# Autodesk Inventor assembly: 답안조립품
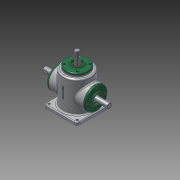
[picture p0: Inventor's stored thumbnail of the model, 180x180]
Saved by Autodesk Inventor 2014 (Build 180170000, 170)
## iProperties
Created: 2015-10
Part Number: 답안조립품
Document SubType Name: Assembly
Designer: Administrator
Author: Administrator
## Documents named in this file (14)
- C:\Users\Administrator\Desktop\451007V1019\답안조립품.iam
- C:\Users\Administrator\Desktop\451007V1019\1-본체.ipt
- C:\Users\Administrator\Desktop\451007V1019\M4.ipt
- C:\Users\Administrator\Desktop\451007V1019\메인 베벨기어.ipt
- C:\Users\Administrator\Desktop\451007V1019\메인 축.ipt
- 메인 축.ipt
- C:\Users\Administrator\Desktop\451007V1019\베어링 6203.ipt
- C:\Users\Administrator\Desktop\451007V1019\서브 베벨기어.ipt
- C:\Users\Administrator\Desktop\451007V1019\서브 축.ipt
- 서브 축.ipt
- C:\Users\Administrator\Desktop\451007V1019\오일실.ipt
- C:\Users\Administrator\Desktop\451007V1019\커버.ipt
- C:\Users\Administrator\Desktop\451007V1019\키 4x4.ipt
- C:\Users\Administrator\Desktop\451007V1019\키 5x5.ipt
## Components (7 placed, 2 different names)
1. 1-본체:1
2. M4:2
3. M4:3
4. M4:1
5. M4:4
6. M4:5
7. M4:6
## Named parameters: d38_d35 = 0, d39_d36 = 0, d40_d37 = 0, d41_d14 = 0, d42_d15 = 0, d43_d16 = 0, d44_d17 = 0, d45_d20 = 0, d46_d21 = 0, d47_d34 = 0
